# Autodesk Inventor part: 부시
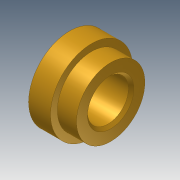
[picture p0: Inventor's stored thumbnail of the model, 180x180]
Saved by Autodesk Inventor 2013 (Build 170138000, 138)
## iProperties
Company: 한국ATC센터
Created: 2014-08
Part Number: 부시
Document SubType Name: Modeling
Designer: KYOUNG IL JANG
Density: 1 g/cm^3
Checked By: KYOUNG IL JANG
Material: 일반
Mass: 6.39105 g
Surface Area: 30.183 cm^2
Volume: 6.39105 cm^3
Author: KYOUNG IL JANG
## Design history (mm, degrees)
sketch "스케치1"
  geometry: L1 (0, 0)-(15, 0); L2 (0, 7.5)-(15, 7.5); L3 (15, 7.5)-(15, 12.5); L4 (15, 12.5)-(8, 12.5); L5 (8, 12.5)-(8, 15); L6 (8, 15)-(0, 15); L7 (0, 15)-(0, 7.5)
  constraints: 14 end point, 4 parallel, 2 vertical alignment, 1 horizontal, 1 perpendicular, 1 vertical
  dimensions: "d0" = 15 distance of L1.start L1.end; "d1" = 15 diameter of L2 L1; "d2" = 25 diameter of L4 L1; "d3" = 8 distance of L5.end L6.end; "d4" = 30 diameter of L6 L1
revolve "회전1" sketch "스케치1" stored, may be unused: angle "d5" = 90 deg
chamfer "모따기1" distance "d6" = 1; stored, may be unused: second distance "d7" = 2, angle "d8" = 45 deg
node "솔리드1"
